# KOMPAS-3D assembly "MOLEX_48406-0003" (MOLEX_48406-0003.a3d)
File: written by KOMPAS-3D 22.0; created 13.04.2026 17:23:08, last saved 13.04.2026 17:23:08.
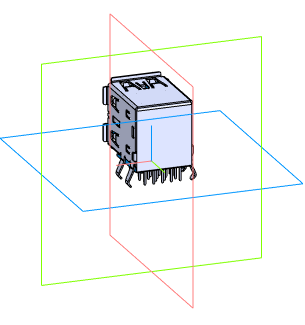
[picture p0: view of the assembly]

Document properties: Автор: Andrey; Полное имя файла: C:\Users\User1\Documents\MOLEX_48406-0003.a3d

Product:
- Component [detail]: SS-52000-003  | qty 1  | source file: SS-52000-003.m3d
- Part/product: MOLEX_48406-0003
    Комментарий: MOLEX_48406-0003

Referenced files in C:\Users\User1\Documents\: SS-52000-003.m3d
